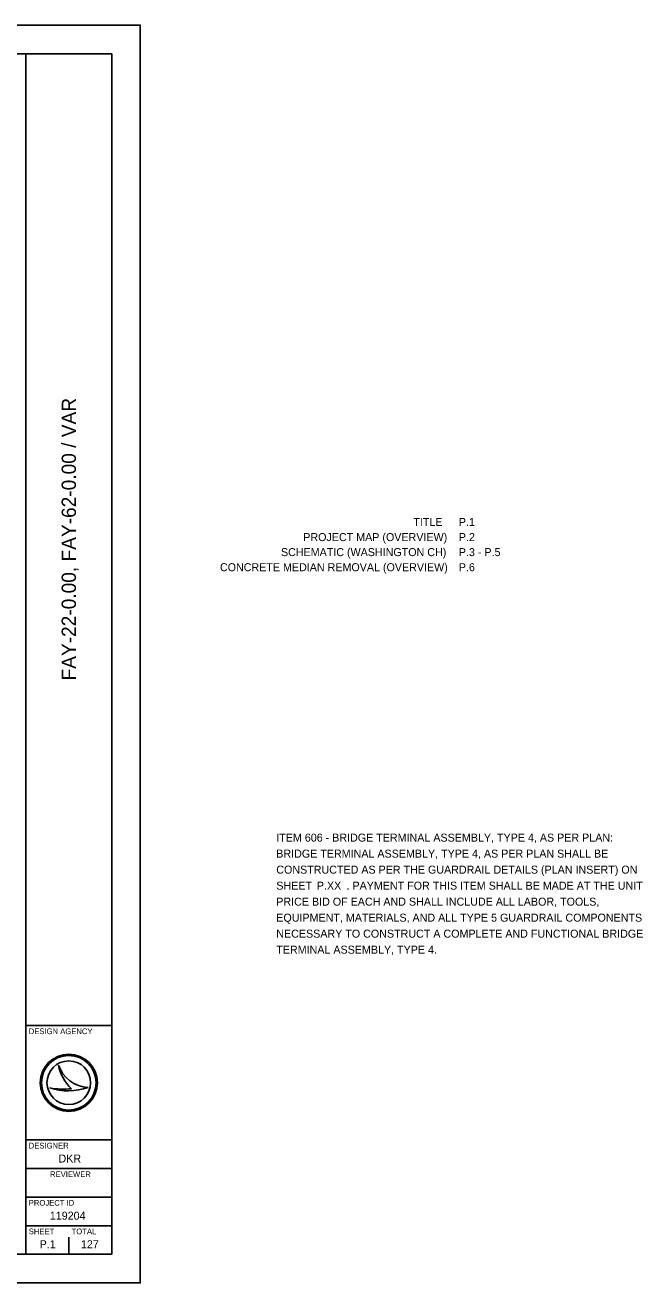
# Model space of a CAD drawing. Extents: x -12 to 164, y -741 to 24.
# Drawn here: x 31.99 to 42.79, y 0 to 22 of the extents above; entities that cross this region are included whole.
import ezdxf

# ---------------------------------------------------------------- set-up
doc = ezdxf.new("R2010")
doc.units = 0
for name, color, linetype in [('Default', 7, 'Continuous'), ('PM_X_CL_Pass_Proh_Rt', 7, 'Continuous'), ('SC_Scratch1', 7, 'Continuous'), ('SH_Border', 7, 'Continuous'), ('SH_Cut_Line', 7, 'Continuous'), ('SH_Data', 7, 'Continuous')]:
    doc.layers.add(name, color=color, linetype=linetype)

msp = doc.modelspace()

# ---------------------------------------------------------------- linework, layer by layer
at = {"layer": 'SH_Border'}
for p, q in [((32, 0.5), (32, 21.5)), ((32, 4.5), (33.5, 4.5)), ((32, 2.5), (33.5, 2.5)), ((32, 2), (33.5, 2)), ((32, 1.5), (33.5, 1.5)), ((32, 1), (33.5, 1))]:
    msp.add_line(p, q, dxfattribs=at)
msp.add_lwpolyline([(1.5, 21.5), (33.5, 21.5), (33.5, 0.5), (1.5, 0.5)], close=True, dxfattribs=at)
at = {"layer": 'SH_Cut_Line'}
msp.add_lwpolyline([(0, 0), (34, 0), (34, 22), (0, 22)], close=True, dxfattribs=at)
at = {"layer": 'SH_Data'}
for p, q in [((32.567, 3.81), (32.567, 3.81)), ((32.417, 3.41), (32.417, 3.41)), ((32.75, 3.5), (32.75, 3.5)), ((33.087, 3.419), (33.087, 3.419)), ((32.375, 0.675), (32.375, 0.675)), ((32.75, 0.5), (32.75, 0.8))]:
    msp.add_line(p, q, dxfattribs=at)
for radius in [0.5, 0.477, 0.477, 0.382]:
    msp.add_circle((32.75, 3.5), radius, dxfattribs=at)
for centre, radius, start, end in [((33.116, 3.998), 0.58, 198.9257, 198.9319), ((33.347, 3.97), 0.796, 191.6379, 191.6421), ((33.116, 3.998), 0.58, 198.9319, 267.1657), ((33.347, 3.97), 0.796, 191.6421, 226.0947), ((32.739, 4.37), 1.013, 251.4576, 290.0832), ((32.648, 4.654), 1.266, 259.4964, 259.4995), ((32.739, 4.37), 1.013, 251.4527, 251.4576), ((32.648, 4.654), 1.266, 259.4995, 276.6672)]:
    msp.add_arc(centre, radius, start, end, dxfattribs=at)

# ---------------------------------------------------------------- texts
at = {"layer": 'Default'}
for s, p in [('TITLE', (38.774, 13.239)), ('PROJECT MAP (OVERVIEW)', (36.85, 12.975)), ('SCHEMATIC (WASHINGTON CH)', (36.46, 12.712)), ('CONCRETE MEDIAN REMOVAL (OVERVIEW)', (35.393, 12.448))]:
    msp.add_text(s, height=0.14, dxfattribs=at).set_placement(p)
at = {"layer": 'PM_X_CL_Pass_Proh_Rt'}
for s, p in [('P.1', (39.57, 13.239)), ('P.2', (39.57, 12.975)), ('P.3 - P.5', (39.57, 12.712)), ('P.6', (39.57, 12.448))]:
    msp.add_text(s, height=0.14, dxfattribs=at).set_placement(p)
at = {"layer": 'SC_Scratch1'}
for s, p in [('ITEM 606 - BRIDGE TERMINAL ASSEMBLY, TYPE 4, AS PER PLAN:', (36.378, 7.718)), ('BRIDGE TERMINAL ASSEMBLY, TYPE 4, AS PER PLAN SHALL BE ', (36.378, 7.438)), ('CONSTRUCTED AS PER THE GUARDRAIL DETAILS (PLAN INSERT) ON ', (36.378, 7.158)), ('SHEET   ', (36.378, 6.878)), ('P.XX  ', (37.087, 6.878)), ('. PAYMENT FOR THIS ITEM SHALL BE MADE AT THE UNIT ', (37.606, 6.878)), ('PRICE BID OF EACH AND SHALL INCLUDE ALL LABOR, TOOLS, ', (36.378, 6.598)), ('EQUIPMENT, MATERIALS, AND ALL TYPE 5 GUARDRAIL COMPONENTS ', (36.378, 6.318)), ('NECESSARY TO CONSTRUCT A COMPLETE AND FUNCTIONAL BRIDGE ', (36.378, 6.038)), ('TERMINAL ASSEMBLY, TYPE 4. ', (36.378, 5.758))]:
    msp.add_text(s, height=0.14, dxfattribs=at).set_placement(p)
at = {"layer": 'SH_Data'}
msp.add_text('FAY-22-0.00, FAY-62-0.00 / VAR', height=0.25, rotation=90, dxfattribs=at).set_placement((32.875, 10.537))
for s, height, p in [('DESIGN AGENCY', 0.1, (32.05, 4.35)), ('DESIGNER', 0.1, (32.05, 2.35)), ('DKR', 0.14, (32.569, 2.105)), ('REVIEWER', 0.1, (32.422, 1.85)), ('PROJECT ID', 0.1, (32.05, 1.35)), ('119204', 0.14, (32.418, 1.105)), ('SHEET', 0.1, (32.05, 0.85)), ('TOTAL', 0.1, (32.8, 0.85)), ('P.1', 0.14, (32.24, 0.605)), ('127', 0.14, (32.962, 0.605))]:
    msp.add_text(s, height=height, dxfattribs=at).set_placement(p)

doc.saveas('drawing.dxf')
